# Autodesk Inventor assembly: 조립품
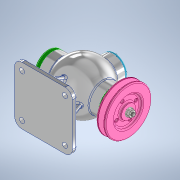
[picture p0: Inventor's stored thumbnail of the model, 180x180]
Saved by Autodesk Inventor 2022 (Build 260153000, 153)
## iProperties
Created: 2024-04
Part Number: 조립품
Document SubType Name: Assembly
Designer: user
Author: user
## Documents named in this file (16)
- C:\Users\user\Desktop\740406V1011\조립품.iam
- C:\Users\user\Desktop\740406V1011\본체.ipt
- C:\Users\user\Desktop\740406V1011\뒤커버.ipt
- C:\Users\user\Desktop\740406V1011\앞커버.ipt
- C:\Users\user\Desktop\740406V1011\상부커버.ipt
- C:\Users\user\Desktop\740406V1011\베어링- 6202.ipt
- KS B 2023 - 6202 - 15 x 35 x 11 - 7.8.ipt
- C:\Users\user\Desktop\740406V1011\칼라.ipt
- C:\Users\user\Desktop\740406V1011\편심축.ipt
- C:\Users\user\Desktop\740406V1011\키 4 x 4 x 12.ipt
- C:\Users\user\Desktop\740406V1011\오일실 15 30 7.ipt
- C:\Users\user\Desktop\740406V1011\V-벨트풀리.ipt
- C:\Users\user\Desktop\740406V1011\너트 M8.ipt
- C:\Users\user\Desktop\740406V1011\볼트 M4 x 16.ipt
- C:\Users\user\Desktop\740406V1011\볼트 M4 x 12.ipt
- C:\Users\user\Desktop\740406V1011\슬라이드.ipt
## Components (15 placed, 4 different names)
1. KS B 2023 - 6202 - 15 x 35 x 11 - 7.8:1
2. KS B 2023 - 6202 - 15 x 35 x 11 - 7.8:2
3. V-벨트풀리:1
4. ISO 4762 M4 x 16:1
5. ISO 4762 M4 x 16:2
6. ISO 4762 M4 x 16:3
7. ISO 4762 M4 x 16:4
8. ISO 4762 M4 x 16:5
9. ISO 4762 M4 x 16:6
10. ISO 4762 M4 x 16:7
11. ISO 4762 M4 x 16:8
12. KS B 1021 - 에 따름 ISO 1207 - 미터 A  M 4 x 12:1
13. KS B 1021 - 에 따름 ISO 1207 - 미터 A  M 4 x 12:2
14. KS B 1021 - 에 따름 ISO 1207 - 미터 A  M 4 x 12:3
15. KS B 1021 - 에 따름 ISO 1207 - 미터 A  M 4 x 12:4
